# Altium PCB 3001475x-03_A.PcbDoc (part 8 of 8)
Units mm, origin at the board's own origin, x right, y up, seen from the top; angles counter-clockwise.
Board outline 100 x 72 mm, 12 copper layers (Top Layer, L2 GND, Layer 3, L4 GND, Layer 5, L6 PWR, L7 3V3, Layer 8, L9 GND, Layer 10, L11 GND, Bottom Layer), stack 1.735 mm thick; 428 components, 499 nets, 1973 pads, 1473 vias.
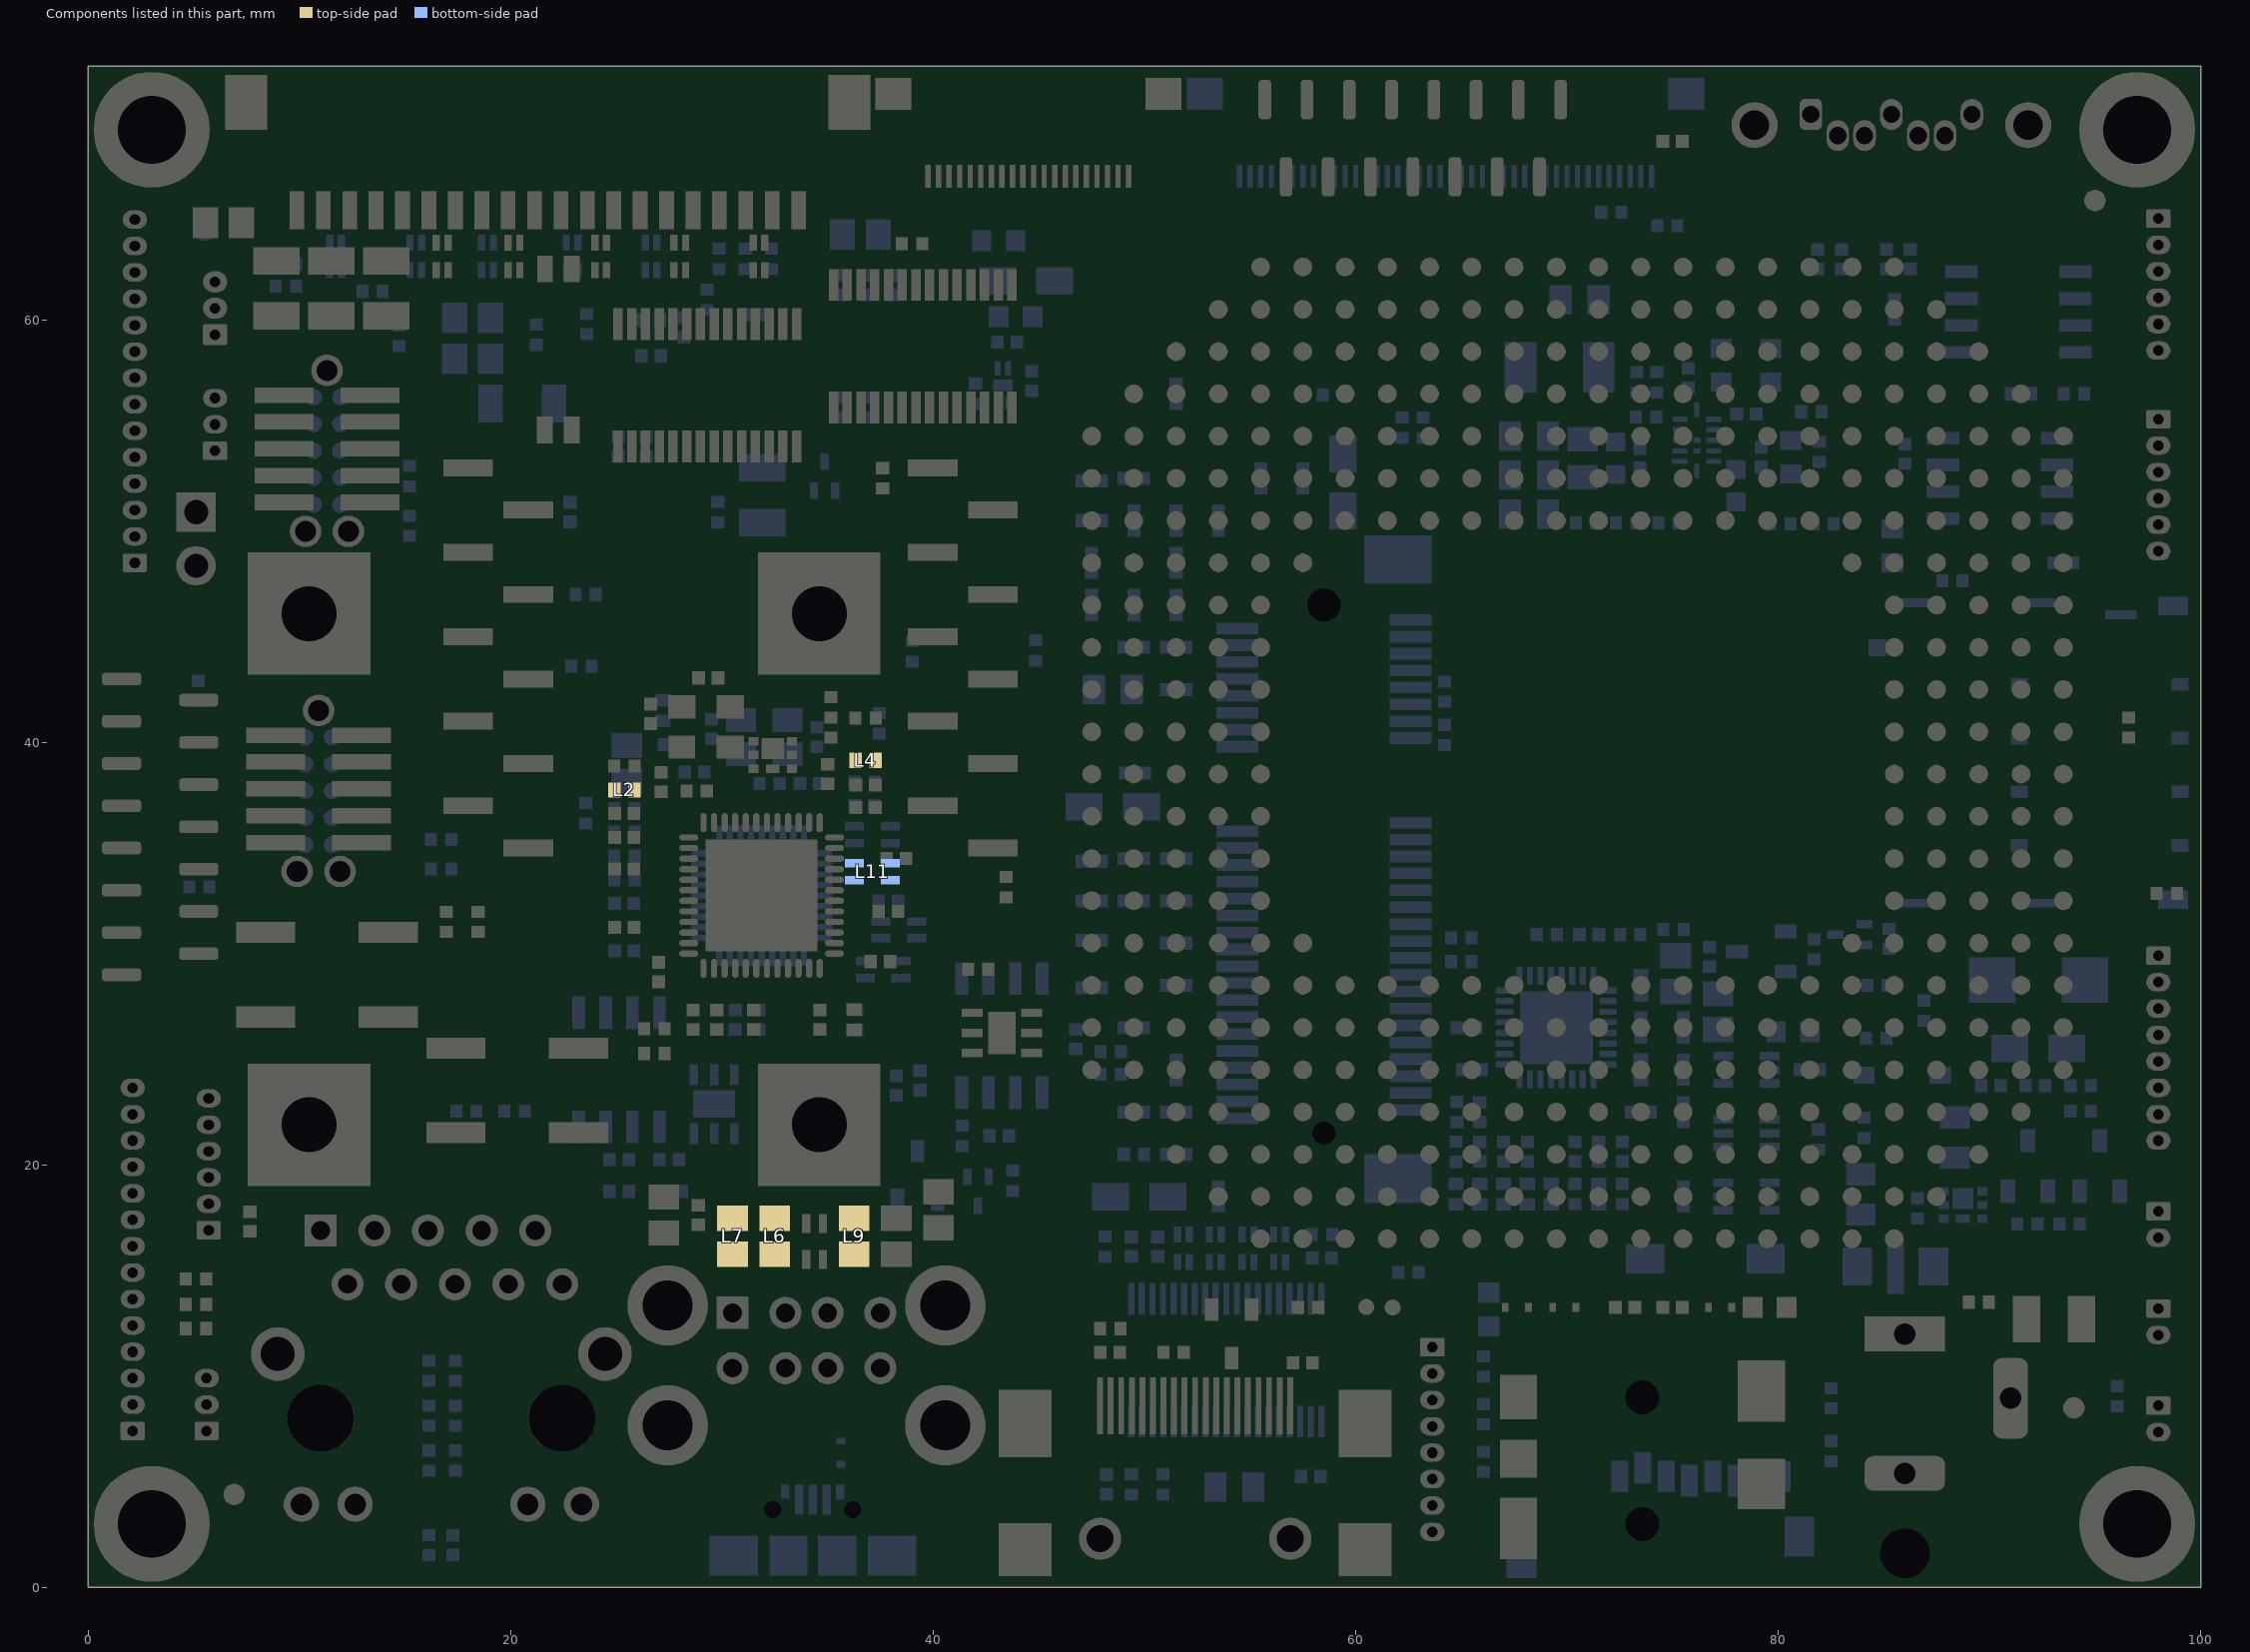
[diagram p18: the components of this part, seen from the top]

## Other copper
Top Layer:
  pour cut-out: 65,49.5 65,31.75 82.5,31.75 82.5,49.5
  text "30014752-03_TOP" at 23.175,49.75 h0.63
  text "REV A" at 25.9,48.4 h0.63
  text "CCIMX6" at 25.3,45.75 h0.75
  text "SBC" at 26.6,44.65 h0.75
  text ".Layer_Name" at 41.25,-18.875 h2.54
Layer 8:
  pour cut-out: 82.5,31.75 82.5,49.5 65,49.5 65,31.75
  text ".Layer_Name" at 41.047,-19 h2.54
Layer 5:
  pour cut-out: 82.5,49.5 65,49.5 65,31.75 82.5,31.75
  text ".Layer_Name" at 42.625,-19 h2.54
Layer 10:
  pour cut-out: 65,31.75 82.5,31.75 82.5,49.5 65,49.5
  text ".Layer_Name" at 41.25,-18.875 h2.54
L6 PWR:
  text ".Layer_Name" at 44.125,-19.375 h2.54
Layer 3:
  pour cut-out: 65,49.5 65,31.75 82.5,31.75 82.5,49.5
  text ".Layer_Name" at 42.5,-19 h2.54
Bottom Layer:
  pour cut-out: 82.5,49.5 65,49.5 65,31.75 82.5,31.75
  text "CCIMX6_SBC" at 23.6,31.1 h1
  text "30014752-03_BOT" at 0.75,30.1 h1 r270
  text "REV A" at 16,28.85 h1
  text ".Layer_Name" at 37.526,-19 h2.54
L2 GND (plane layer: these items are gaps in the copper):
  lines w0.6: 7.775,0 7.775,9.225 6.875,10.125 6.875,11.875 8.1,13.1 9.75,13.1 11,11.85 11,7.8 10.9,7.7 10.875,7.725 9,7.725 9.025,7.7 9.025,2 24.575,2 24.575,5.225 24.025,5.225 24.025,9.2 22.85,10.375 22.85,11.7 23.7,12.55 25.25,12.55 25.225,12.575 25.225,14.275 26.525,15.575 28.3,15.575 29.525,14.35 29.525,9.7 29.9,9.325 30.75,9.325 30.775,9.3 30.775,3.125 37.875,3.125 37.9,3.15 37.9,9.15 38.475,9.725 38.475,14.425 39.6,15.55 41.55,15.55 46.5,10.6 46.5,2.5 46.55,2.45 56.625,2.45 56.625,4.35 56.65,4.375 58.875,4.375 58.875,9.475 62.375,9.475 62.375,1.95 66.125,1.95 66.125,3.125 69.525,3.125 69.525,2.1 78.95,2.1 78.95,3.2 78.975,3.225 83.25,3.225 83.25,0
L4 GND (plane layer: these items are gaps in the copper):
  lines w0.5: 64.85,20.7 64.85,23.65 64.93,23.73 66.07,23.73 66.55,23.25 71.6,23.25 71.6,26.5 73.4,26.5 73.4,29 76.65,29 76.65,25.8 74.15,25.8 74.15,16.15 72.825,16.15 72.825,12.575 72.85,12.55 74.75,12.55 74.75,13.8 76.9,13.8 76.9,11.65 69.35,11.65 69.35,4.25 66.05,4.25 66.05,13.25 66.05,17.375 69.6,17.375 69.6,20.7 64.85,20.7
  lines w0.6: 7.775,0 7.775,9.225 6.875,10.125 6.875,11.875 8.1,13.1 9.75,13.1 11,11.85 11,7.8 10.9,7.7 10.875,7.725 9,7.725 9.025,7.7 9.025,2 24.575,2 24.575,5.225 24.025,5.225 24.025,9.2 22.85,10.375 22.85,11.7 23.7,12.55 25.25,12.55 25.225,12.575 25.225,14.275 26.525,15.575 28.3,15.575 29.525,14.35 29.525,9.7 29.9,9.325 30.75,9.325 30.775,9.3 30.775,3.125 37.875,3.125 37.9,3.15 37.9,9.15 38.475,9.725 38.475,14.425 39.6,15.55 41.55,15.55 46.5,10.6 46.5,2.5 46.55,2.45 56.625,2.45 56.625,4.35 56.65,4.375 58.875,4.375 58.875,9.475 62.375,9.475 62.375,1.95 66.125,1.95 66.125,3.125 69.525,3.125 69.525,2.1 78.95,2.1 78.95,3.2 78.975,3.225 83.25,3.225 83.25,0
L7 3V3 (plane layer: these items are gaps in the copper):
  lines w0.6: 7.775,0 7.775,9.225 6.875,10.125 6.875,11.875 8.1,13.1 9.75,13.1 11,11.85 11,7.8 10.9,7.7 10.875,7.725 9,7.725 9.025,7.7 9.025,2 24.575,2 24.575,5.225 24.025,5.225 24.025,9.2 22.85,10.375 22.85,11.7 23.7,12.55 25.25,12.55 25.225,12.575 25.225,14.275 26.525,15.575 28.3,15.575 29.525,14.35 29.525,9.7 29.9,9.325 30.75,9.325 30.775,9.3 30.775,3.125 37.875,3.125 37.9,3.15 37.9,9.15 38.475,9.725 38.475,14.425 39.6,15.55 41.55,15.55 46.5,10.6 46.5,2.5 46.55,2.45 56.625,2.45 56.625,4.35 56.65,4.375 58.875,4.375 58.875,9.475 62.375,9.475 62.375,1.95 66.125,1.95 66.125,3.125 69.525,3.125 69.525,2.1 78.95,2.1 78.95,3.2 78.975,3.225 83.25,3.225 83.25,0
  lines w2: 0.502,0.502 0.502,71.498 99.498,71.498 99.498,0.502 ; 1.305,70.495 99.498,70.495
L9 GND (plane layer: these items are gaps in the copper):
  lines w0.6: 7.775,0 7.775,9.225 6.875,10.125 6.875,11.875 8.1,13.1 9.75,13.1 11,11.85 11,7.8 10.9,7.7 10.875,7.725 9,7.725 9.025,7.7 9.025,2 24.575,2 24.575,5.225 24.025,5.225 24.025,9.2 22.85,10.375 22.85,11.7 23.7,12.55 25.25,12.55 25.225,12.575 25.225,14.275 26.525,15.575 28.3,15.575 29.525,14.35 29.525,9.7 29.9,9.325 30.75,9.325 30.775,9.3 30.775,3.125 37.875,3.125 37.9,3.15 37.9,9.15 38.475,9.725 38.475,14.425 39.6,15.55 41.55,15.55 46.5,10.6 46.5,2.5 46.55,2.45 56.625,2.45 56.625,4.35 56.65,4.375 58.875,4.375 58.875,9.475 62.375,9.475 62.375,1.95 66.125,1.95 66.125,3.125 69.525,3.125 69.525,2.1 78.95,2.1 78.95,3.2 78.975,3.225 83.25,3.225 83.25,0
L11 GND (plane layer: these items are gaps in the copper):
  lines w0.6: 7.775,0 7.775,9.225 6.875,10.125 6.875,11.875 8.1,13.1 9.75,13.1 11,11.85 11,7.8 10.9,7.7 10.875,7.725 9,7.725 9.025,7.7 9.025,2 24.575,2 24.575,5.225 24.025,5.225 24.025,9.2 22.85,10.375 22.85,11.7 23.7,12.55 25.25,12.55 25.225,12.575 25.225,14.275 26.525,15.575 28.3,15.575 29.525,14.35 29.525,9.7 29.9,9.325 30.75,9.325 30.775,9.3 30.775,3.125 37.875,3.125 37.9,3.15 37.9,9.15 38.475,9.725 38.475,14.425 39.6,15.55 41.55,15.55 46.5,10.6 46.5,2.5 46.55,2.45 56.625,2.45 56.625,4.35 56.65,4.375 58.875,4.375 58.875,9.475 62.375,9.475 62.375,1.95 66.125,1.95 66.125,3.125 69.525,3.125 69.525,2.1 78.95,2.1 78.95,3.2 78.975,3.225 83.25,3.225 83.25,0

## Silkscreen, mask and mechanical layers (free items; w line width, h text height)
Top Overlay:
  circle w0.6: c92.275,3.15 r0.3
  region: 7.4,50.35 7.4,51.35 6.4,50.85
  region: 22.2,52.55 22.2,53.55 21.2,53.05
  region: 16.7,50.8 16.7,51.8 15.7,51.3
  region: 8,41.5 8,42.5 7,42
  region: 6.3,40.85 6.3,39.85 7.3,40.35
  region: 35.35,64.35 35.35,65.35 34.35,64.85
  region: 50.75,65 51.75,65 51.25,66
  region: 71.4,65.65 72.4,65.65 71.9,66.65
  lines w0.25: 19.295,36.3 19.295,27.663 23.85,27.663 ; 19.3,37.675 19.3,40.325 ; 19.3,41.675 19.3,44.325 ; 19.3,45.675 19.3,48.325 ; 19.3,49.675 19.3,52.325 ; 19.824,54.427 19.295,54 ; 20.28,54.794 27.485,60.603 35.602,60.603 40.072,56.947 ; 26.35,27.663 28.025,27.663 ; 30.325,27.663 30.925,27.663 ; 32.075,27.663 34.05,27.663 ; 35.2,27.663 35.625,27.663 ; 36.9,27.663 43.675,27.663 43.675,34.325 ; 42.657,54.833 43.675,54 43.675,51.675 ; 43.675,35.675 43.675,38.325 ; 43.675,39.675 43.675,42.325 ; 43.675,43.675 43.675,46.325 ; 43.675,47.675 43.675,50.325 ; 19.295,54 19.295,53.65 19.295,54
  lines w0.254: 91.075,1.475 91.875,1.475 ; 91.275,3.124 cw(c92.275,3.15) 93.275,3.175 ; 91.475,1.075 91.475,1.875 ; 91.675,4.875 91.675,5.675 ; 92.275,1.075 92.275,2.575 ; 92.275,4.15 92.275,5.65
  text "UART" at 3.55,65.5 h1.2
  text "MIPI CSI" at 54.85,64.65 h2
  text "SATA" at 89.8,64.55 h1.5
  text "CSI0" at 41.8,62.9 h2
  text "LVDS0" at 33.1,62.7 h2
  text "BOOT" at 16.2,59.8 h2
  text "PWR" at 3.9,59.6 h0.9 r90
  text "CAN" at 96.825,58.525 h2 r90
  text "LE0" at 7.8,58.5 h1.5
  text "LE1" at 10.4,58.5 h1.5
  text "LE2" at 13,58.5 h1.5
  text "SWD" at 15.7,55.4 h2
  text "CONS" at 7.8,53.6 h1.2 r90
  text "I2C" at 96.825,49.025 h2 r90
  text "MIPI DSI" at 7.325,42.6 h2 r90
  text "JTAG" at 13.2,33.4 h2
  text "ON/OFF" at 8.95,31.95 h1.5
  text "XBEE" at 20.4,30.775 h1.8
  text "MODULE" at 19.925,29.025 h1.8
  text "GPIO" at 5.7,25.2 h1.5
  text "SPI" at 96.75,23.9 h2 r90
  text "RESET" at 13.6,23.6 h1.5
  text "GbE" at 14,19.3 h2
  text "5V" at 96.85,16.55 h2 r90
  text "for i.MX6 SBC" at 45.025,14.35 h1.8 r90
  text "USB" at 8.15,14.05 h1.5 r90
  text "CONNECT CORE" at 43.7,13.825 h1.8 r90
  text "PWR" at 85.45,13.1 h2
  text "AUDIO" at 62.225,13.025 h2
  text "3.3V" at 96.55,11.3 h2 r90
  text "HEADPHONE" at 80.475,10.425 h2 r270
  text "HDMI" at 46.85,10.2 h2 r90
  text "USB" at 43.6,9.55 h2 r90
  text "BATT" at 96.55,6.4 h2 r90
  text "XBEE" at 8,5.9 h1.5 r90
  text "5VDC" at 91.4,5.9 h2
  text ".Layer_Name" at 36.905,-19.012 h2.54
Bottom Overlay:
  region: 40.15,64.45 39.15,64.45 39.65,65.45
  region: 54.9,64.45 53.9,64.45 54.4,65.45
  region: 8.1,64.05 8.1,65.05 9.1,64.55
  text "CSI1" at 48.85,64 h2
  text "LCD" at 64.7,63.15 h2
  text "LVDS1" at 33.45,58.15 h2
  text "Mini" at 54.3,37.9 h2
  text "PCIe" at 54.225,36.4 h2
  text "MICRO SIM" at 98.05,31 h1.5
  text "MICRO SD" at 82.65,16.6 h1.8 r90
  text "USB OTG" at 44.85,3.275 h2
  text ".Layer_Name" at 36.742,-18.873 h2.54
Top Paste:
  text ".Layer_Name" at 39.548,-18.889 h2.54
Bottom Paste:
  text ".Layer_Name" at 37.409,-19.018 h2.54
Top Solder:
  text ".Layer_Name" at 38.026,-18.881 h2.54
Bottom Solder:
  text ".Layer_Name" at 37.014,-19.018 h2.54
Panel Outline:
  lines w0.25: 192.5,74.5 215,74.5 cw(c215,73.25) 215,72 205,72 205,62 cw(c203.75,62) 202.5,62 202.5,72 192.54,72 cw(c192.54,73.25) 192.54,74.5 ; 287.5,72 222.5,72 cw(c222.5,73.25) 222.5,74.5 287.5,74.5 ; 287.58,72 ccw(c287.58,73.25) 287.58,74.5 ; 295,72 305,72 305,62 ccw(c306.25,62) 307.5,62 307.5,72 ccw(c305,72) 305,74.5 295,74.5 ; 295.08,72 cw(c295.08,73.25) 295.08,74.5 ; 60.975,0 cw(c60.975,-1.25) 62.225,-1.25 ; 60.975,0 cw(c60.975,-1.25) 62.225,-1.25 ; 60.975,0 0,0 0,10 ccw(c-1.25,10) -2.5,10 -2.5,-2.75 ccw(c-1.25,-2.75) -1.25,-4 60.975,-4 ccw(c60.975,-2.75) 62.225,-2.75 62.225,-1.25 ; 66.225,-1.25 cw(c67.475,-1.25) 67.475,0 ; 66.225,-1.25 cw(c67.475,-1.25) 67.475,0 ; 66.225,-1.25 66.225,-2.75 ccw(c67.475,-2.75) 67.475,-4 93,-4 163.475,-4 ccw(c163.475,-2.75) 164.725,-2.75 164.725,-1.25 ccw(c163.475,-1.25) 163.475,0 102.5,0 102.5,10 ccw(c101.25,10) 100,10 100,0 67.475,0 ; -15,-11.5 320,-11.5 320,79.5 -15,79.5 -15,-11.5 ; -2.5,17.5 ccw(c-1.25,17.5) 0,17.5 0,54.5 ccw(c-1.25,54.5) -2.5,54.5 -2.5,17.5 ; -2.5,62 ccw(c-1.25,62) 0,62 0,72 10,72 ccw(c10,73.25) 10,74.5 0,74.5 ccw(c0,72) -2.5,72 -2.5,62 ; 17.5,72 cw(c17.5,73.25) 17.5,74.5 82.5,74.5 cw(c82.5,73.25) 82.5,72 17.5,72 ; 65.5,32.25 82,32.25 82,49 65.5,49 65.5,32.25 ; 90,72 cw(c90,73.25) 90,74.5 112.54,74.5 cw(c112.54,73.25) 112.54,72 102.5,72 102.5,62 cw(c101.25,62) 100,62 100,72 90,72 ; 100,16.25 ccw(c101.25,16.25) 102.5,16.25 102.5,54.5 ccw(c101.25,54.5) 100,54.5 100,16.25 ; 120,72 cw(c120,73.25) 120,74.5 185,74.5 cw(c185,73.25) 185,72 120,72 ; 168.725,-2.75 ccw(c169.975,-2.75) 169.975,-4 266.05,-4 ccw(c266.05,-2.75) 267.3,-2.75 267.3,-1.25 ccw(c266.05,-1.25) 266.05,0 205,0 205,10 ccw(c203.75,10) 202.5,10 202.5,0 169.975,0 ccw(c169.975,-1.25) 168.725,-1.25 168.725,-2.75 ; 202.5,16.25 ccw(c203.75,16.25) 205,16.25 205,54.5 ccw(c203.75,54.5) 202.5,54.5 202.5,16.25 ; 271.3,-2.75 ccw(c272.55,-2.75) 272.55,-4 306.25,-4 ccw(c306.25,-2.75) 307.5,-2.75 307.5,10 ccw(c306.25,10) 305,10 305,0 272.55,0 ccw(c272.55,-1.25) 271.3,-1.25 271.3,-2.75 ; 305,16.25 ccw(c306.25,16.25) 307.5,16.25 307.5,54.5 ccw(c306.25,54.5) 305,54.5 305,16.25
Top Assembly:
  drawing of 57 lines, arcs and shapes, not listed
  text "2" at 27.482,122.428 h4.57
  text "1" at 179.882,122.428 h4.57
  text "B" at -25.858,75.438 h7.11
  text "B" at 230.682,75.438 h7.11
  text "1. Assemble in accordance with IPC-A-610, class 2." at 110.05,68 h5
  text ".Layer_Name" at 37.8,-19 h2.54
  text "CAD GENERATED:" at 169.214,-30.48 h1.27
  text ".pcb_File_Name_No_Path" at 184.708,-30.48 h2.17
  text "A" at -25.858,-31.242 h7.11
  text "A" at 230.682,-31.242 h7.11
  text "EXCEPT AS MAY BE OTHERWISE PROVIDED BY" at 70.154,-34.544 h2.17
  text "WIRELESS DESIGN SERVICES" at 164.134,-36.068 h2.54
  text "CONTRACT, THIS DOCUMENT IS THE PROPERTY" at 70.154,-36.576 h2.17
  text "OF DIGI INTERNATIONAL.  IF RELEASED TO OTHER" at 70.154,-38.608 h2.17
  text "11001 Bren Road East" at 164.134,-39.624 h2.54
  text "SOURCES, IT SHALL BE RECEIVED BY SUCH" at 70.154,-40.64 h2.17
  text "SOURCES IN TOTAL CONFIDENCE AND SHALL NOT" at 70.154,-42.672 h2.17
  text "Minnetonka, MN 55343" at 164.642,-43.18 h2.54
  text "BE RELEASED TO ANY THIRD PARTY OR PARTIES," at 70.154,-44.704 h2.17
  text "NOR USED FOR MANUFACTURE OR SALE OF THE" at 70.154,-46.736 h2.17
  text "ARTICLES WITHOUT PRIOR WRITTEN" at 70.154,-48.768 h2.17
  text "DIGI INTERNATIONAL" at 160.07,-49.276 h2.54
  text "AUTHORIZATION." at 70.154,-50.8 h2.17
  text "ConnectCore for i.MX6" at 155.498,-53.34 h2.54
  text "ENGINEER" at 69.646,-57.404 h1.27
  text "SINGLE BOARD COMPUTER (SBC)" at 147.37,-57.404 h2.54
  text "Sebastien Meyer" at 86.41,-58.42 h1.27
  text "PCB DESIGNER" at 69.646,-62.484 h1.27
  text "SIZE" at 122.986,-62.484 h1.27
  text "CAGE NO." at 131.114,-62.484 h1.27
  text "ASSM NO." at 159.054,-62.484 h1.27
  text "REV." at 221.03,-62.484 h1.27
  text "Josh Flagstad" at 86.41,-63.5 h1.27
  text ".VariantName" at 180.39,-66.294 h2.54
  text "DATE" at 69.646,-67.056 h1.27
  text "A" at 123.494,-67.056 h2.54
  text "'.VariantRevision'" at 221.03,-67.056 h2.54
  text ".Print_Date" at 86.41,-68.072 h1.27
  text "JIRA EPIC:" at 69.646,-72.136 h1.27
  text "CC6UL-244" at 86.41,-73.66 h1.27
  text ".Print_Scale" at 120.954,-73.66 h1.27
  text "SVN HEAD REV:" at 146.354,-73.66 h1.27
  text ".VersionControl_RevNumber" at 162.102,-73.66 h1.27
  text "SHEET:" at 184.454,-73.66 h1.27
  text "1 OF 1" at 202.996,-73.66 h1.27
  text "2" at 27.482,-80.772 h4.57
  text "1" at 179.882,-80.772 h4.57
Bottom Assembly:
  drawing of 57 lines, arcs and shapes, not listed
  text "1" at 27.382,122.378 h4.57
  text "2" at 179.782,122.378 h4.57
  text "B" at -23.418,75.388 h7.11
  text "B" at 233.122,75.388 h7.11
  text "1. Assemble in accordance with IPC-A-610, class 2." at 211.95,67.95 h5
  text ".Layer_Name" at 70.324,-19.016 h2.54
  text ".Layer_Name" at 70.274,-19.066 h2.54
  text ".pcb_File_Name_No_Path" at 22.556,-30.53 h2.17
  text "CAD GENERATED:" at 38.05,-30.53 h1.27
  text "A" at -23.418,-31.292 h7.11
  text "A" at 233.122,-31.292 h7.11
  text "EXCEPT AS MAY BE OTHERWISE PROVIDED BY" at 137.11,-34.594 h2.17
  text "WIRELESS DESIGN SERVICES" at 43.13,-36.118 h2.54
  text "CONTRACT, THIS DOCUMENT IS THE PROPERTY" at 137.11,-36.626 h2.17
  text "OF DIGI INTERNATIONAL.  IF RELEASED TO OTHER" at 137.11,-38.658 h2.17
  text "11001 Bren Road East" at 43.13,-39.674 h2.54
  text "SOURCES, IT SHALL BE RECEIVED BY SUCH" at 137.11,-40.69 h2.17
  text "SOURCES IN TOTAL CONFIDENCE AND SHALL NOT" at 137.11,-42.722 h2.17
  text "Minnetonka, MN 55343" at 42.622,-43.23 h2.54
  text "BE RELEASED TO ANY THIRD PARTY OR PARTIES," at 137.11,-44.754 h2.17
  text "NOR USED FOR MANUFACTURE OR SALE OF THE" at 137.11,-46.786 h2.17
  text "ARTICLES WITHOUT PRIOR WRITTEN" at 137.11,-48.818 h2.17
  text "DIGI INTERNATIONAL" at 47.194,-49.326 h2.54
  text "AUTHORIZATION." at 137.11,-50.85 h2.17
  text "ConnectCore for i.MX6" at 51.766,-53.39 h2.54
  text "SINGLE BOARD COMPUTER (SBC)" at 59.894,-57.454 h2.54
  text "ENGINEER" at 137.618,-57.454 h1.27
  text "Sebastien Meyer" at 120.854,-58.47 h1.27
  text "REV." at -13.766,-62.534 h1.27
  text "ASSM NO." at 48.21,-62.534 h1.27
  text "CAGE NO." at 76.15,-62.534 h1.27
  text "SIZE" at 84.278,-62.534 h1.27
  text "PCB DESIGNER" at 137.618,-62.534 h1.27
  text "Josh Flagstad" at 120.854,-63.55 h1.27
  text ".VariantName" at 26.874,-66.344 h2.54
  text ".VariantRevision" at -13.766,-67.106 h2.54
  text "A" at 83.77,-67.106 h2.54
  text "DATE" at 137.618,-67.106 h1.27
  text ".Print_Date" at 120.854,-68.122 h1.27
  text "JIRA EPIC:" at 137.618,-72.186 h1.27
  text "1 OF 1" at 4.268,-73.71 h1.27
  text "SHEET:" at 22.81,-73.71 h1.27
  text ".VersionControl_RevNumber" at 45.162,-73.71 h1.27
  text "SVN HEAD REV:" at 60.91,-73.71 h1.27
  text ".Print_Scale" at 86.31,-73.71 h1.27
  text "CC6UL-244" at 120.854,-73.71 h1.27
  text "1" at 27.382,-80.822 h4.57
  text "2" at 179.782,-80.822 h4.57
Board Outline:
  the board outline again, w0.25
PCB Name:
  text "CCIMX6_SBC_0.2" at 36.25,-24.125 h2.54
Sheet Graphics:
  lines w0.127: -76.86,-127.35 -69.24,-127.35 ; -76.86,-0.35 -69.24,-0.35 ; -76.86,126.65 -69.24,126.65 ; 24.74,-254.35 24.74,-246.73 ; 24.74,246.03 24.74,253.65 ; 126.34,-254.35 126.34,-246.73 ; 126.34,246.03 126.34,253.65 ; 227.94,-254.35 227.94,-246.73 ; 227.94,246.03 227.94,253.65 ; 329.54,-254.35 329.54,-246.73 ; 329.54,246.03 329.54,253.65 ; 431.14,-254.35 431.14,-246.73 ; 431.14,246.03 431.14,253.65 ; 532.74,-254.35 532.74,-246.73 ; 532.74,246.03 532.74,253.65 ; 614.02,-239.11 728.32,-239.11 ; 614.02,-231.49 728.32,-231.49 ; 614.02,-223.87 652.12,-223.87 ; 634.34,-254.35 634.34,-246.73 ; 634.34,246.03 634.34,253.65 ; 652.12,-246.73 652.12,-231.49 652.12,-216.25 ; 705.46,-246.73 705.46,-231.49 ; 728.32,-127.35 735.94,-127.35 ; 728.32,-0.35 735.94,-0.35 ; 728.32,126.65 735.94,126.65 ; 614.02,-246.73 614.02,-216.25 ; 614.02,-246.73 728.32,-246.73 ; 614.02,-246.73 578.46,-246.73 578.46,-216.25 614.02,-216.25 ; 614.02,-216.25 652.12,-216.25 ; 652.12,-216.25 728.32,-216.25 728.32,-246.73 ; 728.32,-246.73 728.32,246.03 -69.24,246.03 -69.24,-246.73 728.32,-246.73 ; -76.86,-254.35 -76.86,253.65 735.94,253.65 735.94,-254.35 -76.86,-254.35
  lines w0.345: 12.5,138.399 53.938,138.399 ; 12.5,146.687 53.938,146.687 ; 12.5,154.974 53.938,154.974 ; 12.5,163.262 53.938,163.262 ; 12.5,171.549 53.938,171.549 ; 12.5,179.837 53.938,179.837 ; 12.5,188.125 53.938,188.125 ; 12.5,196.412 53.938,196.412 ; 12.5,204.7 53.938,204.7 ; 12.5,212.987 53.938,212.987 ; 12.5,221.275 53.938,221.275 ; 12.5,229.563 53.938,229.563 ; 12.5,141.162 12.5,143.924 53.938,143.924 53.938,141.162 12.5,141.162 ; 12.5,149.449 12.5,152.212 53.938,152.212 53.938,149.449 12.5,149.449 ; 12.5,157.737 12.5,160.499 53.938,160.499 53.938,157.737 12.5,157.737 ; 12.5,166.024 12.5,168.787 53.938,168.787 53.938,166.024 12.5,166.024 ; 12.5,174.312 12.5,177.075 53.938,177.075 53.938,174.312 12.5,174.312 ; 12.5,182.6 12.5,185.362 53.938,185.362 53.938,182.6 12.5,182.6 ; 12.5,190.887 12.5,193.65 53.938,193.65 53.938,190.887 12.5,190.887 ; 12.5,199.175 12.5,201.937 53.938,201.937 53.938,199.175 12.5,199.175 ; 12.5,207.462 12.5,210.225 53.938,210.225 53.938,207.462 12.5,207.462 ; 12.5,215.75 12.5,218.513 53.938,218.513 53.938,215.75 12.5,215.75 ; 12.5,224.038 12.5,226.8 53.938,226.8 53.938,224.038 12.5,224.038
  text "1" at -26.517,248.824 h1.78
  text "2" at 74.956,248.824 h1.78
  text "3" at 176.429,248.824 h1.78
  text "4" at 278.054,248.824 h1.78
  text "5" at 379.612,248.824 h1.78
  text "6" at 481.17,248.824 h1.78
  text "7" at 582.812,248.824 h1.78
  text "8" at 684.285,248.824 h1.78
  text "NOTES:" at 349.935,228.685 h5.08
  text "L1 -TOP SIDE IMPEDANCE CONTROLLED SIGNAL .051 Cu FINISHED" at 56.701,228.181 h2.07
  text "2116H = .130mm" at -17.35,224.3 h2.07
  text "L2 - GND .0127 Cu" at 56.701,219.894 h2.07
  text "1. Manufacture in accordance with IPC-A-600, class 2 & IPC-6012," at 349.935,219.16 h5.08
  text "Core = .100mm" at -16.65,215.85 h2.07
  text "L3 - IMPEDANCE CONTROLLED SIGNAL .0127 Cu" at 56.701,211.606 h2.07
  text "class 2 the latest standards." at 365.175,209 h5.08
  text "2-1080 = .131mm" at -22.55,207.7 h2.07
  text "L4 - GND .0127 Cu" at 56.701,203.319 h2.07
  text "Core = .100mm" at -16.65,199.95 h2.07
  text "2. Manufacturing process and materials used must comply with ROHS directive" at 349.935,198.84 h5.08
  text "L5- SIGNAL .0127 Cu" at 56.701,195.031 h2.07
  text "2-1080 = .131mm" at -19.25,190.75 h2.07
  text "2002/95/EC." at 365.175,188.68 h5.08
  text "A" at -73.685,187.915 h1.78
  text "A" at 731.495,187.915 h1.78
  text "L6 - SPLIT POWER .0127 Cu" at 56.701,186.743 h2.07
  text "Core = .100mm" at -18.2,182.8 h2.07
  text "3. Material: S1000-2" at 349.935,178.52 h5.08
  text "L7 - 3V PWR .0127 Cu" at 56.701,178.456 h2.07
  text "2-1080 = .131mm" at -18.75,174.15 h2.07
  text "L8 - IMPEDANCE CONTROLLED SIGNAL .0127 Cu" at 56.701,170.168 h2.07
  text "Laminate and prepreg shall be per IPC-4101/126." at 365.175,168.36 h5.08
  text "Core = .100mm" at -17.2,165.9 h2.07
  text "L9 - GND .0127 Cu" at 56.701,161.881 h2.07
  text "4. The original Gerber data must be increased to account for manufacturing" at 349.935,158.2 h5.08
  text "2-1080 = .131mm" at -20,157.75 h2.07
  text "L10 - IMPEDANCE CONTROLLED SIGNAL .0127 Cu" at 56.701,153.593 h2.07
  text "Core = .100mm" at -18.05,149.3 h2.07
  text "etch tolerances.  Nominal track width +/-10% is expected." at 365.175,148.04 h5.08
  text "L11 - GND .0127 Cu" at 56.701,145.305 h2.07
  text "2116H = .130mm" at -18.4,141.35 h2.07
  text "5. Apply E.N.I.G. to all exposed copper per IPC-4552." at 349.935,137.88 h5.08
  text "BOTTOM SIDE - IMPEDANCE CONTROLLED SIGNAL .051 Cu FINISHED" at 56.701,137.018 h2.07
  text "6. Starting copper weight is 1/2 oz. for all layers." at 349.935,127.72 h5.08
  text "7. Prepreg height and dielectric constant are critical items." at 349.935,117.56 h5.08
  text "8. Silkscreen: Apply silkscreen artwork to the top and bottom sides of the" at 349.935,107.4 h5.08
  text "board using non-conductive epoxy ink. Silkscreen color: YELLOW" at 365.175,97.24 h5.08
  text "9. Solder mask: Liquid photo imageable solder mask over bare copper (SMOBC)" at 349.935,87.08 h5.08
  text "Color: GREEN" at 365.175,76.92 h5.08
  text "CUT OUT" at 45.695,72.644 h1.25
  text "CUT OUT" at 1.27,72.593 h1.25
  text "CUT OUT" at 153.492,72.593 h1.25
  text "CUT OUT" at 254.356,72.593 h1.25
  text "10. Gerber file format: 274-X with 4/3 accuracy (XXXX.XXX). Gerber files are" at 349.935,66.76 h5.08
  text "CUT OUT" at 101.981,63.754 h1.25 r90
  text "CUT OUT" at 204.394,63.703 h1.25 r90
  text "CUT OUT" at 306.908,63.043 h1.25 r90
  text "B" at -73.685,60.915 h1.78
  text "B" at 731.495,60.915 h1.78
  text "in mm, NC Drill files in mils with 2/4 accuracy." at 365.175,56.6 h5.08
  text "11. Maximum warp and twist not to exceed .254mm per linear 25.4mm." at 349.935,46.44 h5.08
  text "CUT OUT" at 68.732,39.522 h1.5
  text "12. Vendor UL flame code 94V-0 to be clearly marked on the silkscreen layer" at 349.935,36.28 h5.08
  text "CUT OUT" at 204.445,31.521 h1.25 r90
  text "CUT OUT" at -0.66,30.734 h1.25 r90
  text "CUT OUT" at 306.934,28.245 h1.25 r90
  text "CUT OUT" at 101.981,27.584 h1.25 r90
  text "only." at 369.25,26.625 h5.08
  text "13. Panelization: 3x1 array, step 102.5mm." at 350.185,15.995 h5.08
  text "14. All boards to be 100% electrically tested." at 350.185,5.835 h5.08
  text "CUT OUT" at 25.248,-2.616 h1.5
  text "CUT OUT" at 107.823,-2.718 h1.5
  text "CUT OUT" at 213.639,-2.896 h1.5
  text "CUT OUT" at 286.233,-2.896 h1.5
  text "15. Unused inner layer pads may be removed." at 350.185,-4.325 h5.08
  text "16. Copper thieving is NOT allowed on the PCB." at 350.685,-15.27 h5.08
  text "17. All drilled holes are specified as finished hole size." at 350.685,-25.43 h5.08
  text "18. Via holes .010 and smaller may be plated shut - All other plated holes" at 350.685,-35.59 h5.08
  text "have a +/- 0.003 inch tolerance." at 365.925,-45.75 h5.08
  text "Non-plated =/- 0.0015 unless otherwise specified." at 365.925,-55.91 h5.08
  text "19. Finished board thickness 0.062 =/-0.006 inch tolerance" at 350.685,-66.07 h5.08
  text "C" at -73.685,-66.085 h1.78
  text "C" at 731.495,-66.085 h1.78
  text "20. Slot/Cutout tolerance +/- 0.005." at 350.625,-77.75 h5.08
  text "21. IMPEDANCE CONTROLLED LINES ARE ON L1, L3, L5, L8, L10, & L12" at 350.125,-87.75 h5.08
  text "100 OHM DIFFERENTIAL PAIR EXTERNAL = .104mm LINE/.151mm SPACE" at 365.625,-95.925 h5.08
  text "100 OHM DIFFERENTIAL PAIR INTERNAL = .093mm LINE/.207mm SPACE" at 365.625,-104.925 h5.08
  text "22. IMPEDANCE CONTROLLED LINES ARE ON L1, L3, L5, L8, L10, & L12" at 350.125,-114.275 h5.08
  text "50 OHM SINGLE ENDED EXTERNAL = .200mm LINE" at 364.25,-123.2 h5.08
  text "50 OHM SINGLE ENDED INTERNAL = .103mm LINE" at 364.25,-132.7 h5.08
  text "23. IMPEDANCE CONTROLLED LINES ARE ON L1, L3, L10, & L12." at 347.35,-143.025 h5.08
  text "90 OHM DIFFERENTIAL PAIR EXTERNAL = .137mm LINE/.143mm SPACE" at 365.05,-153.175 h5.08
  text "90 OHM DIFFERENTIAL PAIR INTERNAL = .103mm LINE/.128mm SPACE" at 365.05,-162.175 h5.08
  text "24. IMPEDANCE CONTROLLED LINES ARE ON L1, L8, & L12." at 349,-171.75 h5.08
  text "85 OHM DIFFERENTIAL PAIR EXTERNAL = .157mm LINE/.143mm SPACE" at 365.6,-180 h5.08
  text "85 OHM DIFFERENTIAL PAIR INTERNAL = .119mm LINE/.125mm SPACE" at 365.6,-189.5 h5.08
  text "D" at -73.685,-193.085 h1.78
  text "D" at 731.495,-193.085 h1.78
  text "25. Class 2 annular ring is acceptable on .2mm vias with .45mm pad." at 347.65,-198.175 h5.08
  text "26. Vendor to generate netlist from Gerber data." at 348.2,-209.25 h5.08
  text "ENGINEER:" at 615.29,-218.79 h1.14
  text "TITLE:" at 653.39,-218.79 h1.14
  text "Digi" at 683.5,-221.25 h3.17
  text "Daniel Alesanco" at 616.56,-222.346 h1.78
  text "PCB DESIGNER:" at 615.29,-226.283 h1.14
  text "i.MX6x SBC" at 674.375,-228 h3.17
  text "Mark Larson" at 616.56,-229.458 h1.78
  text "DATE:" at 615.29,-234.03 h1.14
  text "PART NO.:" at 653.39,-234.03 h1.14
  text "REV:" at 706.73,-234.03 h1.14
  text "30014752-02" at 672.25,-236.25 h1.78
  text "A" at 718.5,-236.25 h1.78
  text ".Print_Date" at 616.56,-237.078 h1.78
  text "FILE NAME:" at 615.29,-241.65 h1.14
  text "SVN HEAD REV:" at 653.39,-241.65 h1.14
  text "SCALE:" at 706.73,-241.65 h1.14
  text "110 N 5th St.  Suite 400" at 580.365,-242.285 h1.78
  text ".VersionControl_RevNumber" at 668.376,-243.682 h1.78
  text ".PCB_FILE_NAME_NO_PATH" at 616.56,-244.698 h1.78
  text "Minneapolis MN 55403" at 580.365,-245.46 h1.78
  text "1" at -26.517,-251.429 h1.78
  text "2" at 74.956,-251.429 h1.78
  text "3" at 176.429,-251.429 h1.78
  text "4" at 278.054,-251.429 h1.78
  text "5" at 379.612,-251.429 h1.78
  text "6" at 481.17,-251.429 h1.78
  text "7" at 582.812,-251.429 h1.78
  text "8" at 684.285,-251.429 h1.78
Drill Drawing:
  lines w0.1: 61.33,-116.3 208.218,-116.3 ; 61.33,-45.05 208.218,-45.05 ; 74.621,-120.05 74.621,-41.3 ; 90.317,-120.05 90.317,-41.3 ; 118.759,-120.05 118.759,-41.3 ; 147.2,-120.05 147.2,-41.3 ; 177.061,-120.05 177.061,-41.3 ; 189.228,-120.05 189.228,-41.3 ; 61.33,-120.05 208.218,-120.05 208.218,-41.3 61.33,-41.3 61.33,-120.05 ; 62.777,-109.758 64.444,-109.758 63.611,-111.425 62.777,-109.758
  text ".Layer_Name" at 35.736,-19.262 h2.54
  text "Symbol" at 63.58,-43.925 h1.8
  text "Count" at 75.746,-43.925 h1.8
  text "Hole Size" at 91.442,-43.925 h1.8
  text "Hole Length" at 119.884,-43.925 h1.8
  text "Rout Path Length" at 148.325,-43.925 h1.8
  text "Plated" at 178.186,-43.925 h1.8
  text "Hole Type" at 190.353,-43.925 h1.8
  text "1473" at 75.746,-47.675 h1.5
  text "0.200mm (7.87mil)" at 91.442,-47.675 h1.5
  text "-" at 119.884,-47.675 h1.5
  text "-" at 148.325,-47.675 h1.5
  text "PTH" at 178.186,-47.675 h1.5
  text "Round" at 190.353,-47.675 h1.5
  text "W" at 62.955,-47.775 h1.67
  text "77" at 75.746,-51.425 h1.5
  text "0.500mm (19.69mil)" at 91.442,-51.425 h1.5
  text "-" at 119.884,-51.425 h1.5
  text "-" at 148.325,-51.425 h1.5
  text "PTH" at 178.186,-51.425 h1.5
  text "Round" at 190.353,-51.425 h1.5
  text "H" at 62.955,-51.525 h1.67
  text "2" at 75.746,-55.175 h1.5
  text "0.813mm (32.00mil)" at 91.442,-55.175 h1.5
  text "-" at 119.884,-55.175 h1.5
  text "-" at 148.325,-55.175 h1.5
  text "NPTH" at 178.186,-55.175 h1.5
  text "Round" at 190.353,-55.175 h1.5
  text "U" at 62.955,-55.275 h1.67
  text "7" at 75.746,-58.925 h1.5
  text "0.813mm (32.00mil)" at 91.442,-58.925 h1.5
  text "-" at 119.884,-58.925 h1.5
  text "-" at 148.325,-58.925 h1.5
  text "PTH" at 178.186,-58.925 h1.5
  text "Round" at 190.353,-58.925 h1.5
  text "K" at 62.955,-59.025 h1.67
  text "18" at 75.746,-62.675 h1.5
  text "0.889mm (35.00mil)" at 91.442,-62.675 h1.5
  text "-" at 119.884,-62.675 h1.5
  text "-" at 148.325,-62.675 h1.5
  text "PTH" at 178.186,-62.675 h1.5
  text "Round" at 190.353,-62.675 h1.5
  text "N" at 62.955,-62.775 h1.67
  text "6" at 75.746,-66.425 h1.5
  text "0.991mm (39.00mil)" at 91.442,-66.425 h1.5
  text "-" at 119.884,-66.425 h1.5
  text "-" at 148.325,-66.425 h1.5
  text "NPTH" at 178.186,-66.425 h1.5
  text "Round" at 190.353,-66.425 h1.5
  text "G" at 62.955,-66.525 h1.67
  text "4" at 75.746,-70.175 h1.5
  text "1.016mm (40.00mil)" at 91.442,-70.175 h1.5
  text "-" at 119.884,-70.175 h1.5
  text "-" at 148.325,-70.175 h1.5
  text "PTH" at 178.186,-70.175 h1.5
  text "Round" at 190.353,-70.175 h1.5
  text "M" at 62.955,-70.275 h1.67
  text "1" at 75.746,-73.925 h1.5
  text "1.100mm (43.31mil)" at 91.442,-73.925 h1.5
  text "-" at 119.884,-73.925 h1.5
  text "-" at 148.325,-73.925 h1.5
  text "NPTH" at 178.186,-73.925 h1.5
  text "Round" at 190.353,-73.925 h1.5
  text "S" at 62.955,-74.025 h1.67
  text "2" at 75.746,-77.675 h1.5
  text "1.143mm (45.00mil)" at 91.442,-77.675 h1.5
  text "-" at 119.884,-77.675 h1.5
  text "-" at 148.325,-77.675 h1.5
  text "PTH" at 178.186,-77.675 h1.5
  text "Round" at 190.353,-77.675 h1.5
  text "R" at 62.955,-77.775 h1.67
  text "2" at 75.746,-81.425 h1.5
  text "1.270mm (50.00mil)" at 91.442,-81.425 h1.5
  text "-" at 119.884,-81.425 h1.5
  text "-" at 148.325,-81.425 h1.5
  text "NPTH" at 178.186,-81.425 h1.5
  text "Round" at 190.353,-81.425 h1.5
  text "T" at 62.955,-81.525 h1.67
  text "2" at 75.746,-85.175 h1.5
  text "1.397mm (55.00mil)" at 91.442,-85.175 h1.5
  text "-" at 119.884,-85.175 h1.5
  text "-" at 148.325,-85.175 h1.5
  text "PTH" at 178.186,-85.175 h1.5
  text "Round" at 190.353,-85.175 h1.5
  text "J" at 62.955,-85.275 h1.67
  text "3" at 75.746,-88.925 h1.5
  text "1.600mm (62.99mil)" at 91.442,-88.925 h1.5
  text "-" at 119.884,-88.925 h1.5
  text "-" at 148.325,-88.925 h1.5
  text "NPTH" at 178.186,-88.925 h1.5
  text "Round" at 190.353,-88.925 h1.5
  text "Q" at 62.955,-89.025 h1.67
  text "2" at 75.746,-92.675 h1.5
  text "1.600mm (63.00mil)" at 91.442,-92.675 h1.5
  text "-" at 119.884,-92.675 h1.5
  text "-" at 148.325,-92.675 h1.5
  text "PTH" at 178.186,-92.675 h1.5
  text "Round" at 190.353,-92.675 h1.5
  text "L" at 62.955,-92.775 h1.67
  text "1" at 75.746,-96.425 h1.5
  text "2.362mm (93.00mil)" at 91.442,-96.425 h1.5
  text "-" at 119.884,-96.425 h1.5
  text "-" at 148.325,-96.425 h1.5
  text "NPTH" at 178.186,-96.425 h1.5
  text "Round" at 190.353,-96.425 h1.5
  text "P" at 62.955,-96.525 h1.67
  text "4" at 75.746,-100.175 h1.5
  text "2.362mm (93.00mil)" at 91.442,-100.175 h1.5
  text "-" at 119.884,-100.175 h1.5
  text "-" at 148.325,-100.175 h1.5
  text "PTH" at 178.186,-100.175 h1.5
  text "Round" at 190.353,-100.175 h1.5
  text "V" at 62.955,-100.275 h1.67
  text "4" at 75.746,-103.925 h1.5
  text "2.600mm (102.36mil)" at 91.442,-103.925 h1.5
  text "-" at 119.884,-103.925 h1.5
  text "-" at 148.325,-103.925 h1.5
  text "PTH" at 178.186,-103.925 h1.5
  text "Round" at 190.353,-103.925 h1.5
  text "F" at 62.955,-104.025 h1.67
  text "6" at 75.746,-107.675 h1.5
  text "3.175mm (125.00mil)" at 91.442,-107.675 h1.5
  text "-" at 119.884,-107.675 h1.5
  text "-" at 148.325,-107.675 h1.5
  text "NPTH" at 178.186,-107.675 h1.5
  text "Round" at 190.353,-107.675 h1.5
  text "I" at 63.233,-107.775 h1.67
  text "4" at 75.746,-111.425 h1.5
  text "3.200mm (125.98mil)" at 91.442,-111.425 h1.5
  text "-" at 119.884,-111.425 h1.5
  text "-" at 148.325,-111.425 h1.5
  text "PTH" at 178.186,-111.425 h1.5
  text "Round" at 190.353,-111.425 h1.5
  text "3" at 75.746,-115.175 h1.5
  text "1.016mm (40.00mil)" at 91.442,-115.175 h1.5
  text "3.200mm (126.00mil)" at 119.884,-115.175 h1.5
  text "2.184mm (86.00mil)" at 148.325,-115.175 h1.5
  text "PTH" at 178.186,-115.175 h1.5
  text "Slot" at 190.353,-115.175 h1.5
  text "O" at 62.955,-115.275 h1.67
  text "1621 Total" at 75.746,-118.925 h1.5
  text "Slot definitions :" at 63.58,-122.249 h1.5
  text "Rout Path Length" at 88.977,-122.249 h1.5
  text "= Calculated from tool start centre position to tool end centre position." at 113.124,-122.249 h1.5
  text "Hole Length" at 88.977,-124.449 h1.5
  text "= Rout Path Length + Tool Size = Slot length as defined in the PCB layout" at 105.877,-124.449 h1.5

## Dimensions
0,72 to 100,72 on Sheet Graphics
0,72 to 102.5,72 on Sheet Graphics
202.5,72 to 205,72 on Sheet Graphics
0,72 to 0,0 on Sheet Graphics
-15,79.5 to 0,72 on Sheet Graphics
-15,79.5 to 320,79.5 on Sheet Graphics
-15,79.5 to -15,-11.5 on Sheet Graphics
-15,-11.5 to 0,0 on Sheet Graphics
305,0 to 306.25,-4 on Sheet Graphics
